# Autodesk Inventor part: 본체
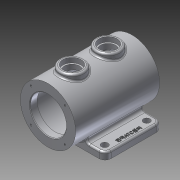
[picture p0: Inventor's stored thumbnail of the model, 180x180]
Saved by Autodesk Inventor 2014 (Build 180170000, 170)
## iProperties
Created: 2014-12
Part Number: 본체
Material: 알루미늄 6061
Document SubType Name: Modeling
Designer: Owner
Density: 2.71 g/cm^3
Appearance: 알루미늄 - 평지
Mass: 1281.45 g
Surface Area: 1027.9 cm^2
Volume: 472.861 cm^3
Author: Owner
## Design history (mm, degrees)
sketch "스케치1"
  geometry: C1 r 46 at (0, 0); 1 further point
  constraints: 1 centre point, 1 coincident
  dimensions: "d0" = 92 diameter of C1
extrude "돌출1" new body sketch "스케치1" stored distance "d1" = 140; taper "d2" = 0 deg
node "작업 평면1"
sketch "스케치2"
  geometry: L1 (65, -38)-(65, -50); L2 (65, -50)-(-65, -50); L3 (-65, -50)-(-65, -38); L4 (-65, -38)-(-25.923, -38); L5 (25.923, -38)-(65, -38); A1 r 46 centre (0, 0) between (-25.923, -38) and (25.923, -38) reference; 5 further points
  constraints: 10 end point, 3 midpoint, 3 parallel, 2 horizontal, 2 perpendicular, 2 point on circle, 2 vertical alignment, 1 horizontal alignment
  dimensions: "d4" = 130 distance of L3.end L1.start; "d5" = 12 distance of L1.start L1.end; "d6" = 50 distance from line of L2 point (0, 0)
extrude "돌출2" join sketch "스케치2" distance "d7" = 95; taper "d8" = 0 deg
sketch "스케치3"
  geometry: C1 r 46 at (0, 0) reference; C2 r 30 at (0, 0)
  constraints: 1 centre point, 1 coincident
  dimensions: "d9" = 60 diameter of C2
extrude "돌출3" cut sketch "스케치3" distance "d10" = 12; taper "d11" = 0 deg
sketch "스케치4"
  geometry: C1 r 30 at (0, 0) reference; C2 r 37.5 at (0, 0)
  constraints: 1 centre point, 1 coincident
  dimensions: "d12" = 75 diameter of C2
extrude "돌출4" cut sketch "스케치4" distance "d13" = 116; taper "d14" = 0 deg
node "작업 평면2"
sketch "스케치8"
  geometry: L1 (39.077, 0)-(0, 0) reference; C1 r 5.5 at (26.077, 12.5); 1 further point
  constraints: 1 centre point
  dimensions: "d26" = 11 diameter of C1; "d27" = 52 horizontal distance of C1.centre point (-25.923, 40); "d28" = 12.5 distance from line of L1 C1.centre
extrude "돌출8" cut sketch "스케치8" stored distance "d29" = 8; taper "d30" = 0 deg
sketch "스케치9"
  geometry: L1 (0, 95)-(39.077, 95) reference; C1 r 5.5 at (26.077, 12.5) reference; C2 r 5.5 at (26.077, 82.5); 1 further point
  constraints: 1 centre point, 1 vertical alignment
  dimensions: "d31" = 11 diameter of C2; "d32" = 12.5 distance from line of L1 C2.centre
extrude "돌출9" cut sketch "스케치9" stored distance "d33" = 8; taper "d34" = 0 deg
sketch "스케치10"
  geometry: L1 (0, 0)-(28.284, 28.284); L2 (0, 0)-(40, 0); C1 r 46 at (0, 0) reference; 1 further point
  constraints: 4 end point, 1 coincident, 1 equal length, 1 horizontal
  dimensions: "d35" = 40 distance of L1.start L1.end; "d36" = 45 deg angle of L2 L1
hole "구멍1" sketch "스케치10" at (28.284, 28.284) diameter "d37" = 3.242; stored, may be unused: countersink angle "d41" = 90 deg, drill point angle "d43" = 118 deg; dims "d38" = 8, "d39" = 4, "d40" = 2, "d42" = 10
fillet "모깎기1" dims "d47" = 5
fillet "모깎기2" dims "d48" = 10
fillet "모깎기3" dims "d49" = 3
fillet "모깎기5" dims "d51" = 3
chamfer "모따기1" distance "d52" = 1; stored, may be unused: second distance "d53" = 2, angle "d54" = 45 deg
sketch "스케치11"
  geometry: L1 (23.116, -7)-(23.116, -82) reference; L2 (26.116, -82)-(26.116, -7) reference; 3 further points
  constraints: 1 horizontal alignment, 1 midpoint, 1 other
  dimensions: "d55" = 8 distance from line of L2 point (18.116, -44.5)
feature "엠보싱1" sketch "스케치11" dims "d1" = 140, "d9" = 60, "d56" = 1, "d57" = 0
node "작업 평면3"
sketch "스케치13"
  geometry: L1 (-46, -70)-(46, -70) reference; C1 r 20 at (0, -30); 1 further point
  constraints: 1 centre point, 1 vertical alignment
  dimensions: "d59" = 40 diameter of C1; "d60" = 40 distance from line of L1 C1.centre
extrude "돌출10" join sketch "스케치13" stored distance "d61" = 10; taper "d62" = 0 deg
sketch "스케치14"
  geometry: C1 r 20 at (0, 0) reference; C2 r 15 at (0, 0); 1 further point
  constraints: 1 centre point, 1 coincident
  dimensions: "d63" = 30 diameter of C2
extrude "돌출11" cut sketch "스케치14" distance "d64" = 8; taper "d65" = 0 deg
sketch "스케치15"
  geometry: C1 r 15 at (0, 0) reference; C2 r 12.5 at (0, 0); 1 further point
  constraints: 1 centre point, 1 coincident
  dimensions: "d66" = 25 diameter of C2
extrude "돌출12" cut sketch "스케치15" stored distance "d67" = 8; taper "d68" = 0 deg
fillet "모깎기6" dims "d69" = 3
fillet "모깎기7" dims "d70" = 3
node "솔리드1"
mirror "대칭1"
mirror "대칭3"
pattern_circular "원형 패턴1" dims angle "d45" = 360 deg
mirror "대칭4"
mirror "대칭5"
node "투영된 루프1"
other parameters: "d15" = 53, "d58" = 53
